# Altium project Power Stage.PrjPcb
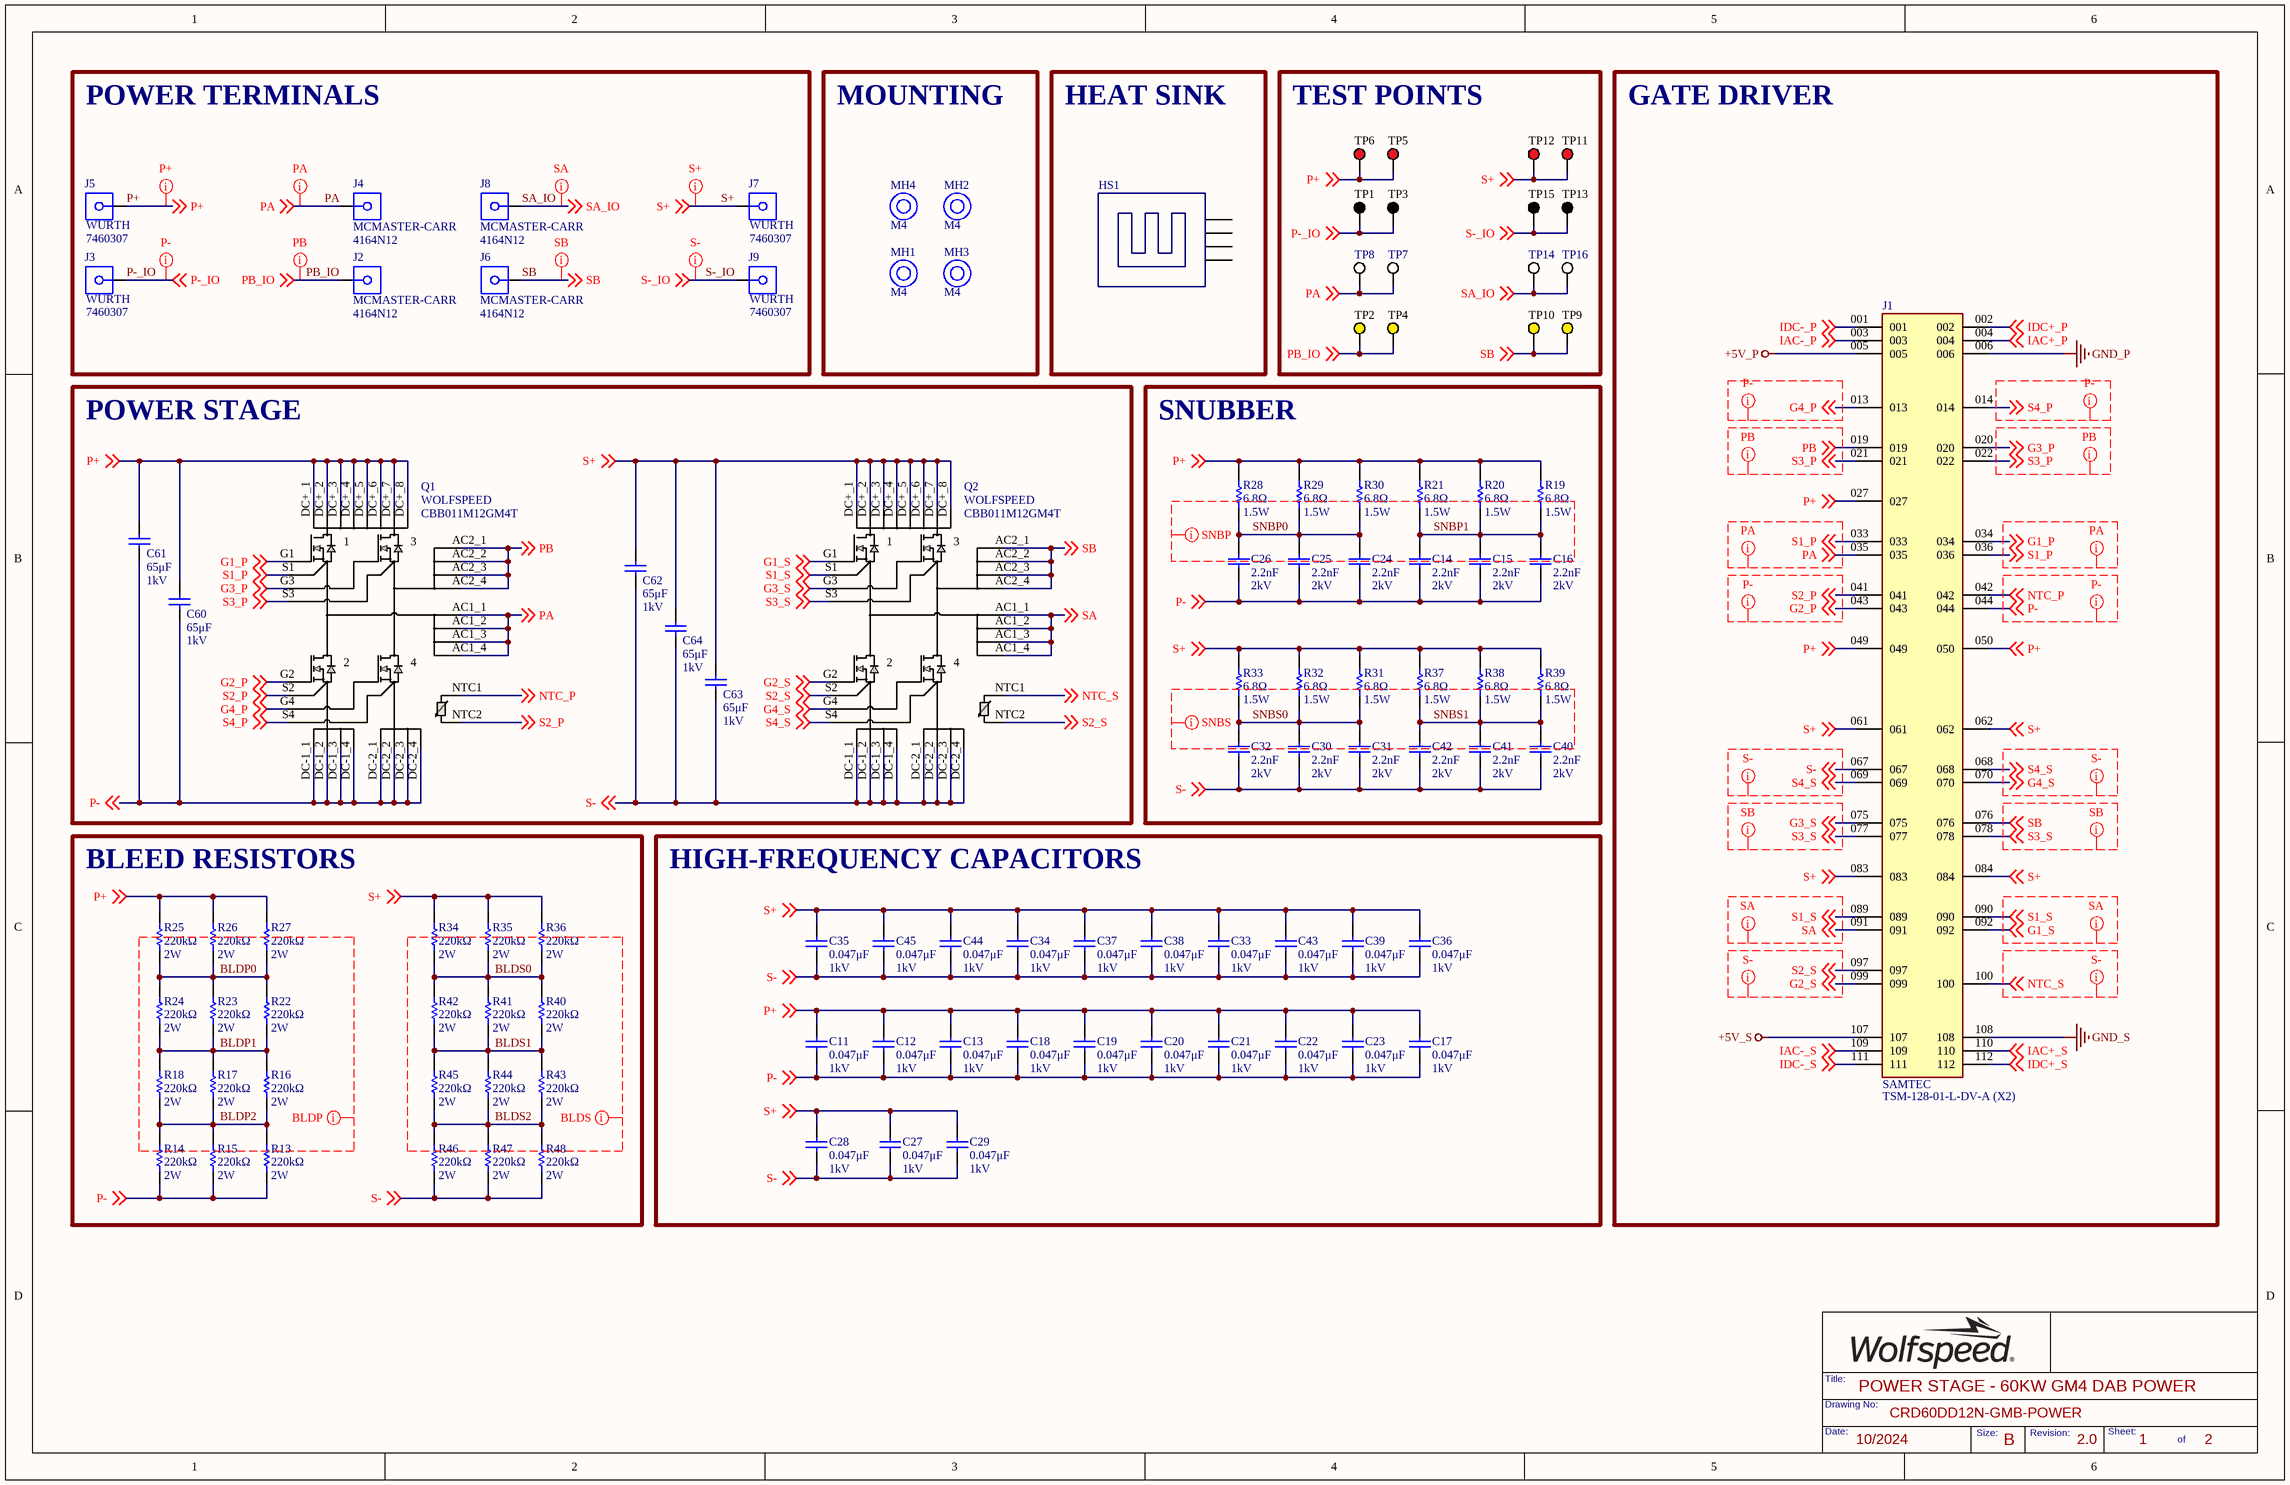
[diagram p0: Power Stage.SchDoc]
2 sheets, 168 parts. Net scope: global (net labels, ports and power ports of the same name join across sheets).
Board file: Power Stage.PcbDoc
Sheets:
  Power Stage.SchDoc
  Current Sense.SchDoc

## Sheet Power Stage.SchDoc: POWER STAGE - 60KW GM4 DAB POWER
size 431 x 279 mm; Date: 10/2024; DocumentNumber: CRD60DD12N-GMB-POWER; Revision: 2.0; SheetNumber: 1; SheetTotal: 2; SheetSize: B

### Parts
C11  value 0.047μF  Voltage: 1kV  [CAP_LDE_QG_2470_KEM]  (hidden comment: LDEQG2470KA5N00)
C12  value 0.047μF  Voltage: 1kV  [CAP_LDE_QG_2470_KEM]  (hidden comment: LDEQG2470KA5N00)
C13  value 0.047μF  Voltage: 1kV  [CAP_LDE_QG_2470_KEM]  (hidden comment: LDEQG2470KA5N00)
C14  value 2.2nF  Voltage: 2kV  [FP-C5750-280-0_4-IPC_A]  (hidden comment: C2220C222KGRAC7800)
C15  value 2.2nF  Voltage: 2kV  [FP-C5750-280-0_4-IPC_A]  (hidden comment: C2220C222KGRAC7800)
C16  value 2.2nF  Voltage: 2kV  [FP-C5750-280-0_4-IPC_A]  (hidden comment: C2220C222KGRAC7800)
C17  value 0.047μF  Voltage: 1kV  [CAP_LDE_QG_2470_KEM]  (hidden comment: LDEQG2470KA5N00)
C18  value 0.047μF  Voltage: 1kV  [CAP_LDE_QG_2470_KEM]  (hidden comment: LDEQG2470KA5N00)
C19  value 0.047μF  Voltage: 1kV  [CAP_LDE_QG_2470_KEM]  (hidden comment: LDEQG2470KA5N00)
C20  value 0.047μF  Voltage: 1kV  [CAP_LDE_QG_2470_KEM]  (hidden comment: LDEQG2470KA5N00)
C21  value 0.047μF  Voltage: 1kV  [CAP_LDE_QG_2470_KEM]  (hidden comment: LDEQG2470KA5N00)
C22  value 0.047μF  Voltage: 1kV  [CAP_LDE_QG_2470_KEM]  (hidden comment: LDEQG2470KA5N00)
C23  value 0.047μF  Voltage: 1kV  [CAP_LDE_QG_2470_KEM]  (hidden comment: LDEQG2470KA5N00)
C24  value 2.2nF  Voltage: 2kV  [FP-C5750-280-0_4-IPC_A]  (hidden comment: C2220C222KGRAC7800)
C25  value 2.2nF  Voltage: 2kV  [FP-C5750-280-0_4-IPC_A]  (hidden comment: C2220C222KGRAC7800)
C26  value 2.2nF  Voltage: 2kV  [FP-C5750-280-0_4-IPC_A]  (hidden comment: C2220C222KGRAC7800)
C27  value 0.047μF  Voltage: 1kV  [CAP_LDE_QG_2470_KEM]  (hidden comment: LDEQG2470KA5N00)
C28  value 0.047μF  Voltage: 1kV  [CAP_LDE_QG_2470_KEM]  (hidden comment: LDEQG2470KA5N00)
C29  value 0.047μF  Voltage: 1kV  [CAP_LDE_QG_2470_KEM]  (hidden comment: LDEQG2470KA5N00)
C30  value 2.2nF  Voltage: 2kV  [FP-C5750-280-0_4-IPC_A]  (hidden comment: C2220C222KGRAC7800)
C31  value 2.2nF  Voltage: 2kV  [FP-C5750-280-0_4-IPC_A]  (hidden comment: C2220C222KGRAC7800)
C32  value 2.2nF  Voltage: 2kV  [FP-C5750-280-0_4-IPC_A]  (hidden comment: C2220C222KGRAC7800)
C33  value 0.047μF  Voltage: 1kV  [CAP_LDE_QG_2470_KEM]  (hidden comment: LDEQG2470KA5N00)
C34  value 0.047μF  Voltage: 1kV  [CAP_LDE_QG_2470_KEM]  (hidden comment: LDEQG2470KA5N00)
C35  value 0.047μF  Voltage: 1kV  [CAP_LDE_QG_2470_KEM]  (hidden comment: LDEQG2470KA5N00)
C36  value 0.047μF  Voltage: 1kV  [CAP_LDE_QG_2470_KEM]  (hidden comment: LDEQG2470KA5N00)
C37  value 0.047μF  Voltage: 1kV  [CAP_LDE_QG_2470_KEM]  (hidden comment: LDEQG2470KA5N00)
C38  value 0.047μF  Voltage: 1kV  [CAP_LDE_QG_2470_KEM]  (hidden comment: LDEQG2470KA5N00)
C39  value 0.047μF  Voltage: 1kV  [CAP_LDE_QG_2470_KEM]  (hidden comment: LDEQG2470KA5N00)
C40  value 2.2nF  Voltage: 2kV  [FP-C5750-280-0_4-IPC_A]  (hidden comment: C2220C222KGRAC7800)
C41  value 2.2nF  Voltage: 2kV  [FP-C5750-280-0_4-IPC_A]  (hidden comment: C2220C222KGRAC7800)
C42  value 2.2nF  Voltage: 2kV  [FP-C5750-280-0_4-IPC_A]  (hidden comment: C2220C222KGRAC7800)
C43  value 0.047μF  Voltage: 1kV  [CAP_LDE_QG_2470_KEM]  (hidden comment: LDEQG2470KA5N00)
C44  value 0.047μF  Voltage: 1kV  [CAP_LDE_QG_2470_KEM]  (hidden comment: LDEQG2470KA5N00)
C45  value 0.047μF  Voltage: 1kV  [CAP_LDE_QG_2470_KEM]  (hidden comment: LDEQG2470KA5N00)
C60  value 65μF  Voltage: 1kV  [C4AQNEW5650M3BJ]  (hidden comment: C4AQNEW5650M3BJ)
C61  value 65μF  Voltage: 1kV  [C4AQNEW5650M3BJ]  (hidden comment: C4AQNEW5650M3BJ)
C62  value 65μF  Voltage: 1kV  [C4AQNEW5650M3BJ]  (hidden comment: C4AQNEW5650M3BJ)
C63  value 65μF  Voltage: 1kV  [C4AQNEW5650M3BJ]  (hidden comment: C4AQNEW5650M3BJ)
C64  value 65μF  Voltage: 1kV  [C4AQNEW5650M3BJ]  (hidden comment: C4AQNEW5650M3BJ)
HS1  GM_FB_COLDPLATE  [GM_FB_COLDPLATE]  (value not drawn)
J1  TSM-128-01-L-DV-A (X2)  Manufacturer: SAMTEC  [SAMTEC_TSM-128-01-L-DV-A_DUAL_CUSTOM]
J2  Manufacturer: MCMASTER-CARR  [4164N12]  (hidden comment: 416N12)
J3  Manufacturer Print: WURTH  [7460307]  (hidden comment: 7460307)
J4  Manufacturer: MCMASTER-CARR  [4164N12]  (hidden comment: 416N12)
J5  Manufacturer Print: WURTH  [7460307]  (hidden comment: 7460307)
J6  Manufacturer: MCMASTER-CARR  [4164N12]  (hidden comment: 416N12)
J7  Manufacturer Print: WURTH  [7460307]  (hidden comment: 7460307)
J8  Manufacturer: MCMASTER-CARR  [4164N12]  (hidden comment: 416N12)
J9  Manufacturer Print: WURTH  [7460307]  (hidden comment: 7460307)
MH1  Size: M4  [MH_M4_NP]  (hidden comment: MH_M4_NP)
MH2  Size: M4  [MH_M4_NP]  (hidden comment: MH_M4_NP)
MH3  Size: M4  [MH_M4_NP]  (hidden comment: MH_M4_NP)
MH4  Size: M4  [MH_M4_NP]  (hidden comment: MH_M4_NP)
Q1  Manufacturer: WOLFSPEED  Manufacturer Part Number: CBB011M12GM4T  [GM3_FULL-BRIDGE_CRW]  (hidden comment: CBB011M12GM4)
Q2  Manufacturer: WOLFSPEED  Manufacturer Part Number: CBB011M12GM4T  [GM3_FULL-BRIDGE_CRW]  (hidden comment: CBB011M12GM4)
R13  Resistance: 220kΩ  Power Rating: 2W  [FP-CRGP2512-IPC_C]  (hidden comment: CRGP2512F220K)
R14  Resistance: 220kΩ  Power Rating: 2W  [FP-CRGP2512-IPC_C]  (hidden comment: CRGP2512F220K)
R15  Resistance: 220kΩ  Power Rating: 2W  [FP-CRGP2512-IPC_C]  (hidden comment: CRGP2512F220K)
R16  Resistance: 220kΩ  Power Rating: 2W  [FP-CRGP2512-IPC_C]  (hidden comment: CRGP2512F220K)
R17  Resistance: 220kΩ  Power Rating: 2W  [FP-CRGP2512-IPC_C]  (hidden comment: CRGP2512F220K)
R18  Resistance: 220kΩ  Power Rating: 2W  [FP-CRGP2512-IPC_C]  (hidden comment: CRGP2512F220K)
R19  value 6.8Ω  Power: 1.5W  [FP-RMCF2512-IPC_A]  (hidden comment: RPC2512JT6R80)
R20  value 6.8Ω  Power: 1.5W  [FP-RMCF2512-IPC_A]  (hidden comment: RPC2512JT6R80)
R21  value 6.8Ω  Power: 1.5W  [FP-RMCF2512-IPC_A]  (hidden comment: RPC2512JT6R80)
R22  Resistance: 220kΩ  Power Rating: 2W  [FP-CRGP2512-IPC_C]  (hidden comment: CRGP2512F220K)
R23  Resistance: 220kΩ  Power Rating: 2W  [FP-CRGP2512-IPC_C]  (hidden comment: CRGP2512F220K)
R24  Resistance: 220kΩ  Power Rating: 2W  [FP-CRGP2512-IPC_C]  (hidden comment: CRGP2512F220K)
R25  Resistance: 220kΩ  Power Rating: 2W  [FP-CRGP2512-IPC_C]  (hidden comment: CRGP2512F220K)
R26  Resistance: 220kΩ  Power Rating: 2W  [FP-CRGP2512-IPC_C]  (hidden comment: CRGP2512F220K)
R27  Resistance: 220kΩ  Power Rating: 2W  [FP-CRGP2512-IPC_C]  (hidden comment: CRGP2512F220K)
R28  value 6.8Ω  Power: 1.5W  [FP-RMCF2512-IPC_A]  (hidden comment: RPC2512JT6R80)
R29  value 6.8Ω  Power: 1.5W  [FP-RMCF2512-IPC_A]  (hidden comment: RPC2512JT6R80)
R30  value 6.8Ω  Power: 1.5W  [FP-RMCF2512-IPC_A]  (hidden comment: RPC2512JT6R80)
R31  value 6.8Ω  Power: 1.5W  [FP-RMCF2512-IPC_A]  (hidden comment: RPC2512JT6R80)
R32  value 6.8Ω  Power: 1.5W  [FP-RMCF2512-IPC_A]  (hidden comment: RPC2512JT6R80)
R33  value 6.8Ω  Power: 1.5W  [FP-RMCF2512-IPC_A]  (hidden comment: RPC2512JT6R80)
R34  Resistance: 220kΩ  Power Rating: 2W  [FP-CRGP2512-IPC_C]  (hidden comment: CRGP2512F220K)
R35  Resistance: 220kΩ  Power Rating: 2W  [FP-CRGP2512-IPC_C]  (hidden comment: CRGP2512F220K)
R36  Resistance: 220kΩ  Power Rating: 2W  [FP-CRGP2512-IPC_C]  (hidden comment: CRGP2512F220K)
R37  value 6.8Ω  Power: 1.5W  [FP-RMCF2512-IPC_A]  (hidden comment: RPC2512JT6R80)
R38  value 6.8Ω  Power: 1.5W  [FP-RMCF2512-IPC_A]  (hidden comment: RPC2512JT6R80)
R39  value 6.8Ω  Power: 1.5W  [FP-RMCF2512-IPC_A]  (hidden comment: RPC2512JT6R80)
R40  Resistance: 220kΩ  Power Rating: 2W  [FP-CRGP2512-IPC_C]  (hidden comment: CRGP2512F220K)
R41  Resistance: 220kΩ  Power Rating: 2W  [FP-CRGP2512-IPC_C]  (hidden comment: CRGP2512F220K)
R42  Resistance: 220kΩ  Power Rating: 2W  [FP-CRGP2512-IPC_C]  (hidden comment: CRGP2512F220K)
R43  Resistance: 220kΩ  Power Rating: 2W  [FP-CRGP2512-IPC_C]  (hidden comment: CRGP2512F220K)
R44  Resistance: 220kΩ  Power Rating: 2W  [FP-CRGP2512-IPC_C]  (hidden comment: CRGP2512F220K)
R45  Resistance: 220kΩ  Power Rating: 2W  [FP-CRGP2512-IPC_C]  (hidden comment: CRGP2512F220K)
R46  Resistance: 220kΩ  Power Rating: 2W  [FP-CRGP2512-IPC_C]  (hidden comment: CRGP2512F220K)
R47  Resistance: 220kΩ  Power Rating: 2W  [FP-CRGP2512-IPC_C]  (hidden comment: CRGP2512F220K)
R48  Resistance: 220kΩ  Power Rating: 2W  [FP-CRGP2512-IPC_C]  (hidden comment: CRGP2512F220K)
TP1  5011  [KSTN-5011_V]  (value not drawn)
TP2  5014  [KSTN-5014_V]  (value not drawn)
TP3  5011  [KSTN-5011_V]  (value not drawn)
TP4  5014  [KSTN-5014_V]  (value not drawn)
TP5  5010  [KSTN-5010_V]  (value not drawn)
TP6  5010  [KSTN-5010_V]  (value not drawn)
TP7  5012  [KSTN-5012_V]  (value not drawn)
TP8  5012  [KSTN-5012_V]  (value not drawn)
TP9  5014  [KSTN-5014_V]  (value not drawn)
TP10  5014  [KSTN-5014_V]  (value not drawn)
TP11  5010  [KSTN-5010_V]  (value not drawn)
TP12  5010  [KSTN-5010_V]  (value not drawn)
TP13  5011  [KSTN-5011_V]  (value not drawn)
TP14  5012  [KSTN-5012_V]  (value not drawn)
TP15  5011  [KSTN-5011_V]  (value not drawn)
TP16  5012  [KSTN-5012_V]  (value not drawn)

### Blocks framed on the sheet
POWER TERMINALS: J2-J9
MOUNTING: MH1-MH4
HEAT SINK: HS1
TEST POINTS: TP1-TP16
GATE DRIVER: J1
POWER STAGE: C60-C64 Q1 Q2
SNUBBER: C14-C16 C24-C26 C30-C32 C40-C42 R19-R21 R28-R33 R37-R39
BLEED RESISTORS: R13-R18 R22-R27 R34-R36 R40-R48
HIGH-FREQUENCY CAPACITORS: C11-C13 C17-C23 C27-C29 C33-C39 C43-C45

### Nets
+5V_P: J1.005
+5V_S: J1.107
GND_P: J1.006
GND_S: J1.108
BLDP0: R22.2 R23.2 R24.2 R25.1 R26.1 R27.1
BLDP1: R16.2 R17.2 R18.2 R22.1 R23.1 R24.1
BLDP2: R13.2 R14.2 R15.2 R16.1 R17.1 R18.1
BLDS0: R34.1 R35.1 R36.1 R40.2 R41.2 R42.2
BLDS1: R40.1 R41.1 R42.1 R43.2 R44.2 R45.2
BLDS2: R43.1 R44.1 R45.1 R46.2 R47.2 R48.2
G1_P: J1.034 Q1.G1 ; off-sheet G1_P
G1_S: J1.092 Q2.G1 ; off-sheet G1_S
G2_P: J1.043 Q1.G2 ; off-sheet G2_P
G2_S: J1.099 Q2.G2 ; off-sheet G2_S
G3_P: J1.020 Q1.G3 ; off-sheet G3_P
G3_S: J1.075 Q2.G3 ; off-sheet G3_S
G4_P: J1.013 Q1.G4 ; off-sheet G4_P
G4_S: J1.070 Q2.G4 ; off-sheet G4_S
IAC+_P: J1.004 ; off-sheet IAC+_P
IAC+_S: J1.110 ; off-sheet IAC+_S
IAC-_P: J1.003 ; off-sheet IAC-_P
IAC-_S: J1.109 ; off-sheet IAC-_S
IDC+_P: J1.002 ; off-sheet IDC+_P
IDC+_S: J1.112 ; off-sheet IDC+_S
IDC-_P: J1.001 ; off-sheet IDC-_P
IDC-_S: J1.111 ; off-sheet IDC-_S
NTC_P: J1.042 Q1.NTC1 ; off-sheet NTC_P
NTC_S: J1.100 Q2.NTC1 ; off-sheet NTC_S
P+: C11.1 C12.1 C13.1 C17.1 C18.1 C19.1 C20.1 C21.1 C22.1 C23.1 C60.1A,1B C61.1A,1B J1.027 J1.049 J1.050 J5.1,2,3,4,5,6,7,8 Q1.DC+_1 Q1.DC+_2 Q1.DC+_3 Q1.DC+_4 Q1.DC+_5 Q1.DC+_6 Q1.DC+_7 Q1.DC+_8 R19.2 R20.2 R21.2 R25.2 R26.2 R27.2 R28.2 R29.2 R30.2 TP5.1 TP6.1 ; off-sheet P+
P-: C11.2 C12.2 C13.2 C14.2 C15.2 C16.2 C17.2 C18.2 C19.2 C20.2 C21.2 C22.2 C23.2 C24.2 C25.2 C26.2 C60.2A,2B C61.2A,2B J1.044 Q1.DC-1_1 Q1.DC-1_2 Q1.DC-1_3 Q1.DC-1_4 Q1.DC-2_1 Q1.DC-2_2 Q1.DC-2_3 Q1.DC-2_4 R13.1 R14.1 R15.1 ; off-sheet P-
P-_IO: J3.1,2,3,4,5,6,7,8 TP1.1 TP3.1 ; off-sheet P-_IO
PA: J1.035 J4.1 Q1.AC1_1 Q1.AC1_2 Q1.AC1_3 Q1.AC1_4 TP7.1 TP8.1 ; off-sheet PA
PB: J1.019 Q1.AC2_1 Q1.AC2_2 Q1.AC2_3 Q1.AC2_4 ; off-sheet PB
PB_IO: J2.1 TP2.1 TP4.1 ; off-sheet PB_IO
S1_P: J1.033 J1.036 Q1.S1 ; off-sheet S1_P
S1_S: J1.089 J1.090 Q2.S1 ; off-sheet S1_S
S2_P: J1.041 Q1.NTC2 Q1.S2 ; off-sheet S2_P
S2_S: J1.097 Q2.NTC2 Q2.S2 ; off-sheet S2_S
S3_P: J1.021 J1.022 Q1.S3 ; off-sheet S3_P
S3_S: J1.077 J1.078 Q2.S3 ; off-sheet S3_S
S4_P: J1.014 Q1.S4 ; off-sheet S4_P
S4_S: J1.068 J1.069 Q2.S4 ; off-sheet S4_S
S+: C27.1 C28.1 C29.1 C33.1 C34.1 C35.1 C36.1 C37.1 C38.1 C39.1 C43.1 C44.1 C45.1 C62.1A,1B C63.1A,1B C64.1A,1B J1.061 J1.062 J1.083 J1.084 J7.1,2,3,4,5,6,7,8 Q2.DC+_1 Q2.DC+_2 Q2.DC+_3 Q2.DC+_4 Q2.DC+_5 Q2.DC+_6 Q2.DC+_7 Q2.DC+_8 R31.2 R32.2 R33.2 R34.2 R35.2 R36.2 R37.2 R38.2 R39.2 TP11.1 TP12.1 ; off-sheet S+
S-: C27.2 C28.2 C29.2 C30.2 C31.2 C32.2 C33.2 C34.2 C35.2 C36.2 C37.2 C38.2 C39.2 C40.2 C41.2 C42.2 C43.2 C44.2 C45.2 C62.2A,2B C63.2A,2B C64.2A,2B J1.067 Q2.DC-1_1 Q2.DC-1_2 Q2.DC-1_3 Q2.DC-1_4 Q2.DC-2_1 Q2.DC-2_2 Q2.DC-2_3 Q2.DC-2_4 R46.1 R47.1 R48.1 ; off-sheet S-
S-_IO: J9.1,2,3,4,5,6,7,8 TP13.1 TP15.1 ; off-sheet S-_IO
SA: J1.091 Q2.AC1_1 Q2.AC1_2 Q2.AC1_3 Q2.AC1_4 ; off-sheet SA
SA_IO: J8.1 TP14.1 TP16.1 ; off-sheet SA_IO
SB: J1.076 J6.1 Q2.AC2_1 Q2.AC2_2 Q2.AC2_3 Q2.AC2_4 TP9.1 TP10.1 ; off-sheet SB
SNBP0: C24.1 C25.1 C26.1 R28.1 R29.1 R30.1
SNBP1: C14.1 C15.1 C16.1 R19.1 R20.1 R21.1
SNBS0: C30.1 C31.1 C32.1 R31.1 R32.1 R33.1
SNBS1: C40.1 C41.1 C42.1 R37.1 R38.1 R39.1

Not connected (* = marked no-connect by the designer): HS1 1 2 3 4

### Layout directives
net class BLDP_CLASS: BLDP0, BLDP1, BLDP2
net class BLDS_CLASS: BLDS0, BLDS1, BLDS2
net class SNBP_CLASS: SNBP0, SNBP1
net class SNBS_CLASS: SNBS0, SNBS1
net class S+_CLASS: S+
net class PA_CLASS: G1_P, PA, S1_P
net class SA_CLASS: G1_S, S1_S, SA, SA_IO
net class P+_CLASS: P+
net class PB_CLASS: G3_P, PB, PB_IO, S3_P
net class P-_CLASS: G2_P, G4_P, NTC_P, P-, P-_IO, S2_P, S4_P
net class SB_CLASS: G3_S, S3_S, SB
net class S-_CLASS: G2_S, G4_S, NTC_S, S2_S, S4_S, S-, S-_IO

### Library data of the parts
C11-C13 C17-C23 C27-C29 C33-C39 C43-C45 = LDEQG2470KA5N00: CAP FILM 0.047UF 10% 1KVDC 5040; Manufacturer: KEMET
C14-C16 C24-C26 C30-C32 C40-C42 = C2220C222KGRAC7800: CAP CER 2200PF 2KV X7R 2220; Manufacturer: KEMET
C60-C64 = C4AQNEW5650M3BJ: CAP FILM 65UF 5% 1KVDC RADIAL; Manufacturer: KEMET
HS1 = GM_FB_COLDPLATE: CUSTOM; Manufacturer: WOLFSPEED
J1 = TSM-128-01-L-DV-A_DUAL_CUSTOM
J2 J4 J6 J8 = 416N12: BOX SCREW LUG 14-1/0 WIRE
J3 J5 J7 J9 = 7460307: TERM REDCUBE M4 8PIN PCB; Manufacturer: WURTH ELEKTRONIK; Current Rating: 80A; Number of Contacts: 8; Insulation: Non-Insulated
MH1-MH4 = MH_M4_NP: PLASTIC SPACER STUD METRIC THREA; Manufacturer: WURTH ELEKTRONIK; Manufacturer Part Number: 971650485
Q1 Q2 = GM3_HALF-BRIDGE: MOSFET 4N-CH 1200V 100A; Type: DEV
R13-R18 R22-R27 R34-R36 R40-R48 = CRGP2512F220K: RES 220K OHM 1% 2W 2512; Manufacturer: TE; Value: 220kΩ; Temperature Coefficient: ±100ppm/°C; Tolerance: 0.01; Voltage Rating: 500V
R19-R21 R28-R33 R37-R39 = RPC2512JT6R80: RES 6.8 OHM 5% 1.5W 2512; Manufacturer: STACKPOLE
TP1 TP3 TP13 TP15 = CMP-1672-00003-4: PC TEST POINT MULTIPURPOSE BLACK; Manufacturer: KEYSTONE
TP2 TP4 TP9 TP10 = CMP-1672-00006-4: PC TEST POINT MULTIPURPOSE YELLOW; Manufacturer: KEYSTONE
TP5 TP6 TP11 TP12 = CMP-1672-00002-4: PC TEST POINT MULTIPURPOSE RED; Manufacturer: KEYSTONE
TP7 TP8 TP14 TP16 = CMP-1672-00004-4: PC TEST POINT MULTIPURPOSE WHITE; Manufacturer: KEYSTONE

## Sheet Current Sense.SchDoc: CURRENT SENSE - 60KW GM4 DAB POWER
size 431 x 279 mm; Date: 10/2024; DocumentNumber: CRD60DD12N-GMB-POWER; Revision: 2.0; SheetNumber: 2; SheetTotal: 2; SheetSize: B
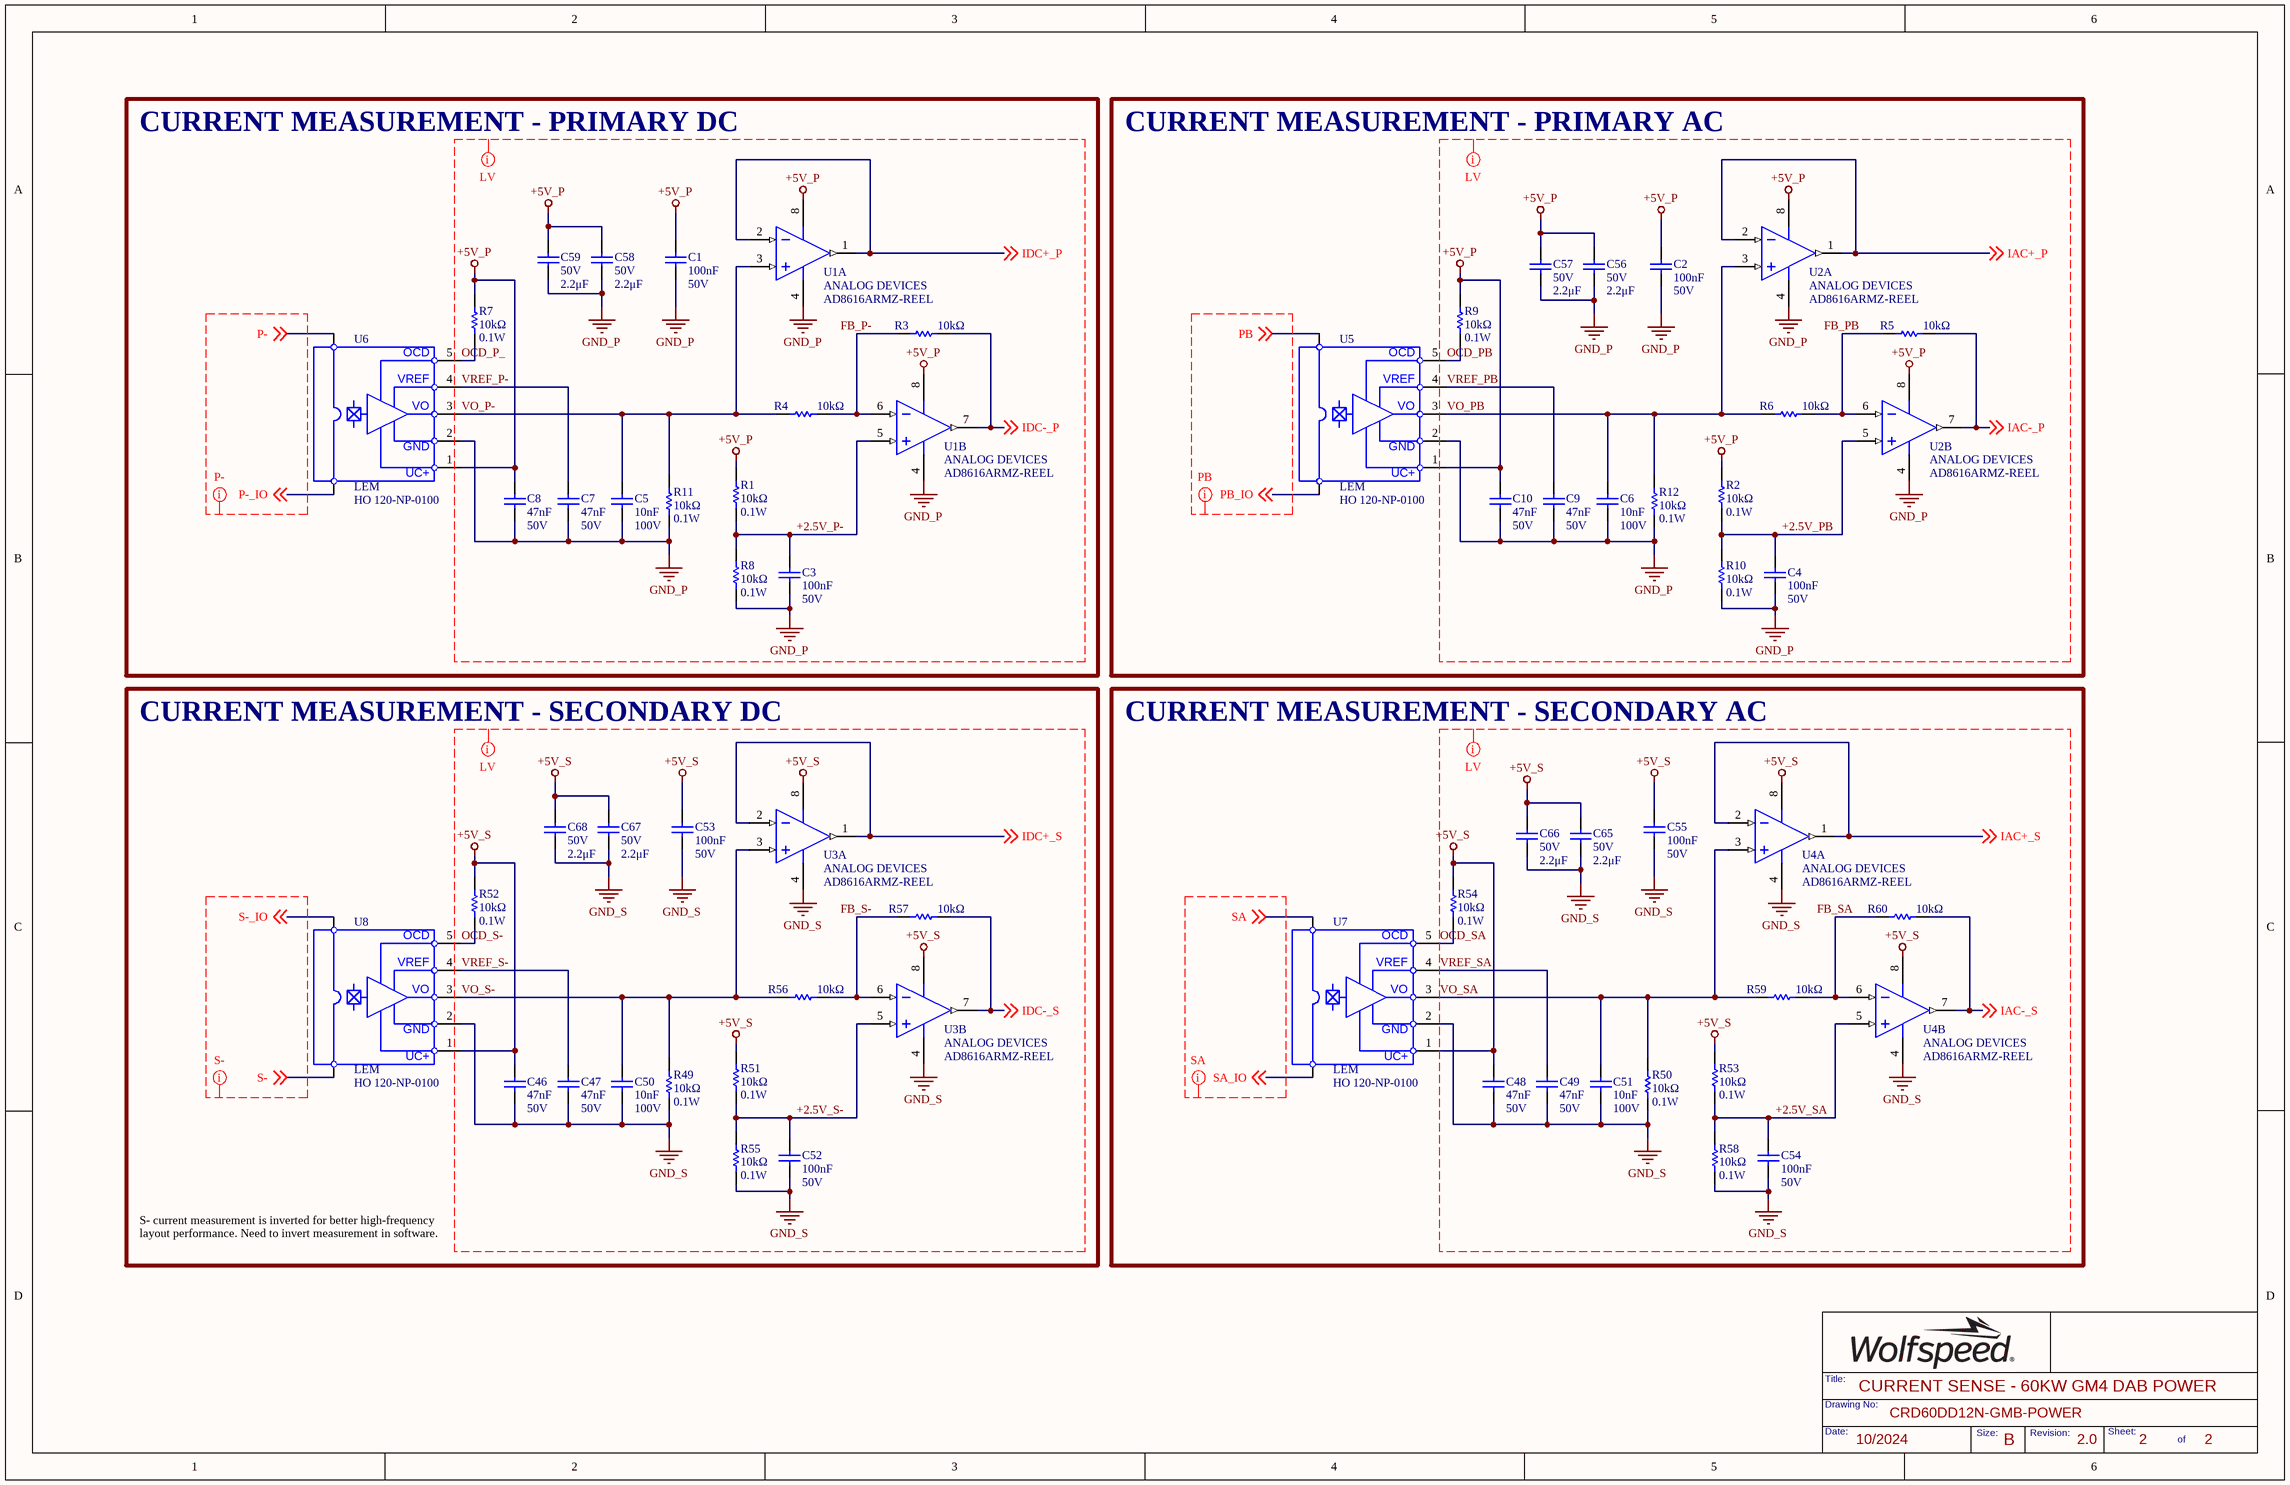
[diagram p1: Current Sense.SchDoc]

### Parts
C1  value 100nF  Voltage: 50V  [FP-C0603C-CF-IPC_B]  (hidden comment: CGA3E2X7R1H104K080AA)
C2  value 100nF  Voltage: 50V  [FP-C0603C-CF-IPC_B]  (hidden comment: CGA3E2X7R1H104K080AA)
C3  value 100nF  Voltage: 50V  [FP-C0603C-CF-IPC_B]  (hidden comment: CGA3E2X7R1H104K080AA)
C4  value 100nF  Voltage: 50V  [FP-C0603C-CF-IPC_B]  (hidden comment: CGA3E2X7R1H104K080AA)
C5  value 10nF  Voltage Rating: 100V  [FP-C0603C-CF-IPC_B]  (hidden comment: GCM188R72A103KA37D)
C6  value 10nF  Voltage Rating: 100V  [FP-C0603C-CF-IPC_B]  (hidden comment: GCM188R72A103KA37D)
C7  value 47nF  Voltage Rating: 50V  [FP-C0603C-CF-IPC_B]  (hidden comment: CGA3E2X7R1H473K080AA)
C8  value 47nF  Voltage Rating: 50V  [FP-C0603C-CF-IPC_B]  (hidden comment: CGA3E2X7R1H473K080AA)
C9  value 47nF  Voltage Rating: 50V  [FP-C0603C-CF-IPC_B]  (hidden comment: CGA3E2X7R1H473K080AA)
C10  value 47nF  Voltage Rating: 50V  [FP-C0603C-CF-IPC_B]  (hidden comment: CGA3E2X7R1H473K080AA)
C46  value 47nF  Voltage Rating: 50V  [FP-C0603C-CF-IPC_B]  (hidden comment: CGA3E2X7R1H473K080AA)
C47  value 47nF  Voltage Rating: 50V  [FP-C0603C-CF-IPC_B]  (hidden comment: CGA3E2X7R1H473K080AA)
C48  value 47nF  Voltage Rating: 50V  [FP-C0603C-CF-IPC_B]  (hidden comment: CGA3E2X7R1H473K080AA)
C49  value 47nF  Voltage Rating: 50V  [FP-C0603C-CF-IPC_B]  (hidden comment: CGA3E2X7R1H473K080AA)
C50  value 10nF  Voltage Rating: 100V  [FP-C0603C-CF-IPC_B]  (hidden comment: GCM188R72A103KA37D)
C51  value 10nF  Voltage Rating: 100V  [FP-C0603C-CF-IPC_B]  (hidden comment: GCM188R72A103KA37D)
C52  value 100nF  Voltage: 50V  [FP-C0603C-CF-IPC_B]  (hidden comment: CGA3E2X7R1H104K080AA)
C53  value 100nF  Voltage: 50V  [FP-C0603C-CF-IPC_B]  (hidden comment: CGA3E2X7R1H104K080AA)
C54  value 100nF  Voltage: 50V  [FP-C0603C-CF-IPC_B]  (hidden comment: CGA3E2X7R1H104K080AA)
C55  value 100nF  Voltage: 50V  [FP-C0603C-CF-IPC_B]  (hidden comment: CGA3E2X7R1H104K080AA)
C56  Voltage Rating: 50V  Capacitance: 2.2μF  [FP-C0603C-CF-IPC_B]  (hidden comment: GRT188R61H225ME13D)
C57  Voltage Rating: 50V  Capacitance: 2.2μF  [FP-C0603C-CF-IPC_B]  (hidden comment: GRT188R61H225ME13D)
C58  Voltage Rating: 50V  Capacitance: 2.2μF  [FP-C0603C-CF-IPC_B]  (hidden comment: GRT188R61H225ME13D)
C59  Voltage Rating: 50V  Capacitance: 2.2μF  [FP-C0603C-CF-IPC_B]  (hidden comment: GRT188R61H225ME13D)
C65  Voltage Rating: 50V  Capacitance: 2.2μF  [FP-C0603C-CF-IPC_B]  (hidden comment: GRT188R61H225ME13D)
C66  Voltage Rating: 50V  Capacitance: 2.2μF  [FP-C0603C-CF-IPC_B]  (hidden comment: GRT188R61H225ME13D)
C67  Voltage Rating: 50V  Capacitance: 2.2μF  [FP-C0603C-CF-IPC_B]  (hidden comment: GRT188R61H225ME13D)
C68  Voltage Rating: 50V  Capacitance: 2.2μF  [FP-C0603C-CF-IPC_B]  (hidden comment: GRT188R61H225ME13D)
R1  value 10kΩ  Max Power Dissipation: 0.1W  [FP-MCR03-IPC_B]  (hidden comment: ERJ3EKF1002V)
R2  value 10kΩ  Max Power Dissipation: 0.1W  [FP-MCR03-IPC_B]  (hidden comment: ERJ3EKF1002V)
R3  value 10kΩ  [FP-MCR03-IPC_B]  (hidden comment: ERJ3EKF1002V)
R4  value 10kΩ  [FP-MCR03-IPC_B]  (hidden comment: ERJ3EKF1002V)
R5  value 10kΩ  [FP-MCR03-IPC_B]  (hidden comment: ERJ3EKF1002V)
R6  value 10kΩ  [FP-MCR03-IPC_B]  (hidden comment: ERJ3EKF1002V)
R7  value 10kΩ  Max Power Dissipation: 0.1W  [FP-MCR03-IPC_B]  (hidden comment: ERJ3EKF1002V)
R8  value 10kΩ  Max Power Dissipation: 0.1W  [FP-MCR03-IPC_B]  (hidden comment: ERJ3EKF1002V)
R9  value 10kΩ  Max Power Dissipation: 0.1W  [FP-MCR03-IPC_B]  (hidden comment: ERJ3EKF1002V)
R10  value 10kΩ  Max Power Dissipation: 0.1W  [FP-MCR03-IPC_B]  (hidden comment: ERJ3EKF1002V)
R11  value 10kΩ  Max Power Dissipation: 0.1W  [FP-MCR03-IPC_B]  (hidden comment: ERJ3EKF1002V)
R12  value 10kΩ  Max Power Dissipation: 0.1W  [FP-MCR03-IPC_B]  (hidden comment: ERJ3EKF1002V)
R49  value 10kΩ  Max Power Dissipation: 0.1W  [FP-MCR03-IPC_B]  (hidden comment: ERJ3EKF1002V)
R50  value 10kΩ  Max Power Dissipation: 0.1W  [FP-MCR03-IPC_B]  (hidden comment: ERJ3EKF1002V)
R51  value 10kΩ  Max Power Dissipation: 0.1W  [FP-MCR03-IPC_B]  (hidden comment: ERJ3EKF1002V)
R52  value 10kΩ  Max Power Dissipation: 0.1W  [FP-MCR03-IPC_B]  (hidden comment: ERJ3EKF1002V)
R53  value 10kΩ  Max Power Dissipation: 0.1W  [FP-MCR03-IPC_B]  (hidden comment: ERJ3EKF1002V)
R54  value 10kΩ  Max Power Dissipation: 0.1W  [FP-MCR03-IPC_B]  (hidden comment: ERJ3EKF1002V)
R55  value 10kΩ  Max Power Dissipation: 0.1W  [FP-MCR03-IPC_B]  (hidden comment: ERJ3EKF1002V)
R56  value 10kΩ  [FP-MCR03-IPC_B]  (hidden comment: ERJ3EKF1002V)
R57  value 10kΩ  [FP-MCR03-IPC_B]  (hidden comment: ERJ3EKF1002V)
R58  value 10kΩ  Max Power Dissipation: 0.1W  [FP-MCR03-IPC_B]  (hidden comment: ERJ3EKF1002V)
R59  value 10kΩ  [FP-MCR03-IPC_B]  (hidden comment: ERJ3EKF1002V)
R60  value 10kΩ  [FP-MCR03-IPC_B]  (hidden comment: ERJ3EKF1002V)
U1  AD8616ARMZ-REEL  Manufacturer: ANALOG DEVICES  [ADI-RM-8_M]  (parts A,B of 2)
U2  AD8616ARMZ-REEL  Manufacturer: ANALOG DEVICES  [ADI-RM-8_M]  (parts A,B of 2)
U3  AD8616ARMZ-REEL  Manufacturer: ANALOG DEVICES  [ADI-RM-8_M]  (parts A,B of 2)
U4  AD8616ARMZ-REEL  Manufacturer: ANALOG DEVICES  [ADI-RM-8_M]  (parts A,B of 2)
U5  Manufacturer: LEM  [HO xx0-NP-0100]  (hidden comment: HO 120-NP-0100)
U6  Manufacturer: LEM  [HO xx0-NP-0100]  (hidden comment: HO 120-NP-0100)
U7  Manufacturer: LEM  [HO xx0-NP-0100]  (hidden comment: HO 120-NP-0100)
U8  Manufacturer: LEM  [HO xx0-NP-0100]  (hidden comment: HO 120-NP-0100)

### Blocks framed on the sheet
CURRENT MEASUREMENT - PRIMARY DC: C1 C3 C5 C7 C8 C58 C59 R1 R3 R4 R7 R8 R11 U1 U6
CURRENT MEASUREMENT - PRIMARY AC: C2 C4 C6 C9 C10 C56 C57 R2 R5 R6 R9 R10 R12 U2 U5
CURRENT MEASUREMENT - SECONDARY DC: C46 C47 C50 C52 C53 C67 C68 R49 R51 R52 R55-R57 U3 U8
CURRENT MEASUREMENT - SECONDARY AC: C48 C49 C51 C54 C55 C65 C66 R50 R53 R54 R58-R60 U4 U7

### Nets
+5V_P: C1.1 C2.1 C8.1 C10.1 C56.1 C57.1 C58.1 C59.1 R1.2 R2.2 R7.2 R9.2 U1.8(+V) U2.8(+V) U5.1(GND) U6.1(GND)
+5V_S: C46.1 C48.1 C53.1 C55.1 C65.1 C66.1 C67.1 C68.1 R51.2 R52.2 R53.2 R54.2 U3.8(+V) U4.8(+V) U7.1(GND) U8.1(GND)
GND_P: C1.2 C2.2 C3.2 C4.2 C5.2 C6.2 C7.2 C8.2 C9.2 C10.2 C56.2 C57.2 C58.2 C59.2 R8.1 R10.1 R11.1 R12.1 U1.4(-V) U2.4(-V) U5.2(OUT-) U6.2(OUT-)
GND_S: C46.2 C47.2 C48.2 C49.2 C50.2 C51.2 C52.2 C53.2 C54.2 C55.2 C65.2 C66.2 C67.2 C68.2 R49.1 R50.1 R55.1 R58.1 U3.4(-V) U4.4(-V) U7.2(OUT-) U8.2(OUT-)
+2.5V_P-: C3.1 R1.1 R8.2 U1.5(+IN_B)
+2.5V_PB: C4.1 R2.1 R10.2 U2.5(+IN_B)
+2.5V_S-: C52.1 R51.1 R55.2 U3.5(+IN_B)
+2.5V_SA: C54.1 R53.1 R58.2 U4.5(+IN_B)
FB_P-: R3.2 R4.1 U1.6(-IN_B)
FB_PB: R5.2 R6.1 U2.6(-IN_B)
FB_S-: R56.1 R57.2 U3.6(-IN_B)
FB_SA: R59.1 R60.2 U4.6(-IN_B)
IAC+_P: U2.1(OUT_A) U2.2(-IN_A) ; off-sheet IAC+_P
IAC+_S: U4.1(OUT_A) U4.2(-IN_A) ; off-sheet IAC+_S
IAC-_P: R5.1 U2.7(OUT_B) ; off-sheet IAC-_P
IAC-_S: R60.1 U4.7(OUT_B) ; off-sheet IAC-_S
IDC+_P: U1.1(OUT_A) U1.2(-IN_A) ; off-sheet IDC+_P
IDC+_S: U3.1(OUT_A) U3.2(-IN_A) ; off-sheet IDC+_S
IDC-_P: R3.1 U1.7(OUT_B) ; off-sheet IDC-_P
IDC-_S: R57.1 U3.7(OUT_B) ; off-sheet IDC-_S
OCD_P_: R7.1 U6.5(VDD)
OCD_PB: R9.1 U5.5(VDD)
OCD_S-: R52.1 U8.5(VDD)
OCD_SA: R54.1 U7.5(VDD)
P-: U6.6,7,8,9(IP+) ; off-sheet P-
P-_IO: U6.10,11,12,13(IP-) ; off-sheet P-_IO
PB: U5.6,7,8,9(IP+) ; off-sheet PB
PB_IO: U5.10,11,12,13(IP-) ; off-sheet PB_IO
S-: U8.10,11,12,13(IP-) ; off-sheet S-
S-_IO: U8.6,7,8,9(IP+) ; off-sheet S-_IO
SA: U7.6,7,8,9(IP+) ; off-sheet SA
SA_IO: U7.10,11,12,13(IP-) ; off-sheet SA_IO
VO_P-: C5.1 R4.2 R11.2 U1.3(+IN_A) U6.3(GND)
VO_PB: C6.1 R6.2 R12.2 U2.3(+IN_A) U5.3(GND)
VO_S-: C50.1 R49.2 R56.2 U3.3(+IN_A) U8.3(GND)
VO_SA: C51.1 R50.2 R59.2 U4.3(+IN_A) U7.3(GND)
VREF_P-: C7.1 U6.4(OUT+)
VREF_PB: C9.1 U5.4(OUT+)
VREF_S-: C47.1 U8.4(OUT+)
VREF_SA: C49.1 U7.4(OUT+)

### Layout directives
net class PB_CLASS: PB, PB_IO
net class P-_CLASS: P-, P-_IO
net class S-_CLASS: S-, S-_IO
net class SA_CLASS: SA, SA_IO
net class LV_CLASS: +2.5V_P-, +2.5V_PB, +2.5V_S-, +2.5V_SA, +5V_P, +5V_S, FB_P-, FB_PB, FB_S-, FB_SA, GND_P, GND_S, IAC+_P, IAC+_S, IAC-_P, IAC-_S, IDC+_P, IDC+_S, IDC-_P, IDC-_S, OCD_P_, OCD_PB, OCD_S-, OCD_SA, VO_P-, VO_PB, VO_S-, VO_SA, VREF_P-, VREF_PB, VREF_S-, VREF_SA

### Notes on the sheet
- S- current measurement is inverted for better high-frequency layout performance. Need to invert measurement in software.

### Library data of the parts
C1-C4 C52-C55 = CGA3E2X7R1H104K080AA: CAP CER 0.1UF 50V X7R 0603; Manufacturer: TDK; Material: 4241ConductorMaterial; Tolerance: 10%
C5 C6 C50 C51 = GCM188R72A103KA37D: CAP CER 10000PF 100V X7R 0603; Manufacturer: MURATA; Material: 4241ConductorMaterial; Tolerance: 10%
C7-C10 C46-C49 = CGA3E2X7R1H473K080AA: CAP CER 0.047UF 50V X7R 0603; Manufacturer: TDK; Material: 4241ConductorMaterial; Tolerance: 10%
C56-C59 C65-C68 = GRT188R61H225ME13D: CAP CER 2.2UF 50V X5R 0603; Manufacturer: MURATA; Tolerance: 20%; Value: 2.2μF
R1-R12 R49-R60 = ERJ3EKF1002V: RES SMD 10K OHM 1% 1/10W 0603; Manufacturer: PANASONIC; Manufacturer Part Number: ERJ-3EKF1002V; Temperature Coefficient: 100ppm/°C; Power Rating: 100mW; Voltage Rating: 75V
U1-U4 = CMP-0384-01706-1: IC CMOS 2 CIRCUIT 8MSOP; Generic Part Number: AD8616; V Span Min: 2.7V; Amplifiers Per Package: 2; V Span Max: 6V; Input Bias Current: 200fA; Input Offset Voltage: 23uV; Iq/Amp: 2mA; Small Signal Bandwidth: 24MHz; Slew Rate: 12V/us
U5-U8 = HO 120-NP-0100: SENSOR CURRENT HALL 120A AC/DC

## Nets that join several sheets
+5V_P: Power Stage (J1.005), Current Sense (16 pins)
+5V_S: Power Stage (J1.107), Current Sense (16 pins)
GND_P: Power Stage (J1.006), Current Sense (22 pins)
GND_S: Power Stage (J1.108), Current Sense (22 pins)
IAC+_P: Power Stage (J1.004), Current Sense (U2.1 U2.2)
IAC+_S: Power Stage (J1.110), Current Sense (U4.1 U4.2)
IAC-_P: Power Stage (J1.003), Current Sense (R5.1 U2.7)
IAC-_S: Power Stage (J1.109), Current Sense (R60.1 U4.7)
IDC+_P: Power Stage (J1.002), Current Sense (U1.1 U1.2)
IDC+_S: Power Stage (J1.112), Current Sense (U3.1 U3.2)
IDC-_P: Power Stage (J1.001), Current Sense (R3.1 U1.7)
IDC-_S: Power Stage (J1.111), Current Sense (R57.1 U3.7)
P-: Power Stage (30 pins), Current Sense (U6.6,7,8,9)
P-_IO: Power Stage (J3.1,2,3,4,5,6,7,8 TP1.1 TP3.1), Current Sense (U6.10,11,12,13)
PB: Power Stage (5 pins), Current Sense (U5.6,7,8,9)
PB_IO: Power Stage (J2.1 TP2.1 TP4.1), Current Sense (U5.10,11,12,13)
S-: Power Stage (34 pins), Current Sense (U8.10,11,12,13)
S-_IO: Power Stage (J9.1,2,3,4,5,6,7,8 TP13.1 TP15.1), Current Sense (U8.6,7,8,9)
SA: Power Stage (5 pins), Current Sense (U7.6,7,8,9)
SA_IO: Power Stage (J8.1 TP14.1 TP16.1), Current Sense (U7.10,11,12,13)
